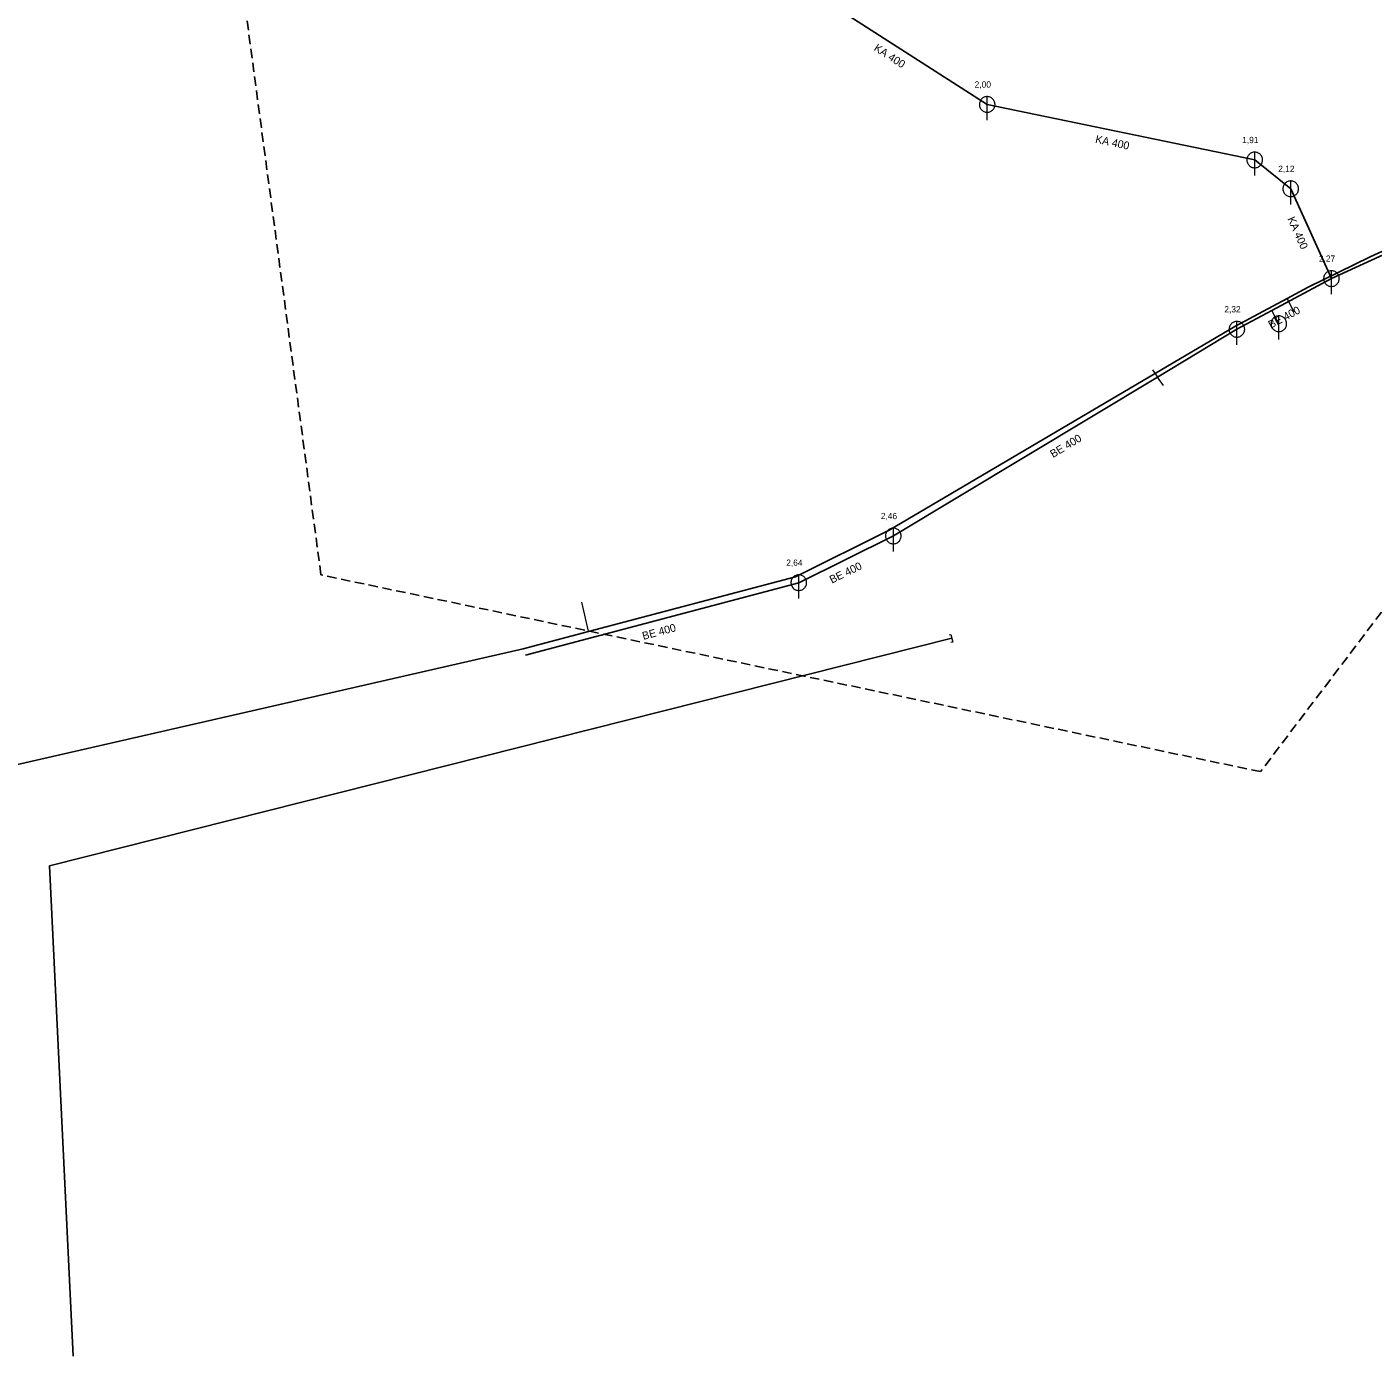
# Model space of a CAD drawing. Extents: x -682839 to -682312, y -994645 to -993949.
# Drawn here: x -682722 to -682550, y -994644.7 to -994475 of the extents above; entities that cross this region are included whole.
import ezdxf

# ---------------------------------------------------------------- set-up
doc = ezdxf.new("R2010")
doc.units = 0
doc.header["$LTSCALE"] = 0.4
doc.linetypes.add('MEDIUM_DASHED', pattern=[4.5, 3, -1.5])
doc.layers.add('1', color=7, linetype='Continuous')
for name, color, linetype, lineweight in [('11', 7, 'Continuous', 13), ('13', 7, 'Continuous', 13), ('14', 7, 'Continuous', 25), ('17', 7, 'Continuous', 25), ('22', 7, 'Continuous', 13), ('34', 7, 'Continuous', 13), ('47', 7, 'Continuous', 13), ('63', 7, 'MEDIUM_DASHED', 25)]:
    doc.layers.add(name, color=color, linetype=linetype, lineweight=lineweight)

msp = doc.modelspace()

# ---------------------------------------------------------------- linework, layer by layer
at = {"layer": '11'}
for p, q in [((-682562.07, -994512.859), (-682562.98, -994511.19)), ((-682578.192, -994518.761), (-682577.559, -994519.67)), ((-682576.8, -994520.77), (-682577.559, -994519.67))]:
    msp.add_line(p, q, dxfattribs=at)
at = {"layer": '13'}
for p, q in [((-682560.989, -994509.68), (-682560.16, -994511.35)), ((-682650.241, -994552.121), (-682651.109, -994548.41))]:
    msp.add_line(p, q, dxfattribs=at)
at = {"layer": '14'}
for p, q in [((-682621.25, -994470.809), (-682599.32, -994484.859)), ((-682599.32, -994484.859), (-682565.149, -994491.949)), ((-682523.789, -994492.6), (-682555.35, -994507.1)), ((-682611.309, -994539.969), (-682623.39, -994545.93)), ((-682623.39, -994545.93), (-682658.3, -994555.18))]:
    msp.add_line(p, q, dxfattribs=at)
at = {"layer": '14', "lineweight": 13}
msp.add_line((-682561.019, -994509.629), (-682560.989, -994509.68), dxfattribs=at)
at = {"layer": '14'}
for points in [[(-682565.149, -994491.949), (-682560.55, -994495.629), (-682555.35, -994507.1)], [(-682555.35, -994507.1), (-682562.98, -994511.19), (-682567.43, -994513.57)], [(-682567.43, -994513.57), (-682577.559, -994519.67), (-682611.309, -994539.969)]]:
    msp.add_lwpolyline(points, dxfattribs=at)
at = {"layer": '17'}
for points in [[(-682545.21, -994501.938), (-682550.42, -994504.32), (-682558.315, -994508.18), (-682561.019, -994509.629), (-682567.699, -994513.21), (-682611.829, -994539.23), (-682623.82, -994545.199), (-682650.23, -994552.17), (-682658.579, -994554.37), (-682723.739, -994569.28), (-682738.277, -994572.726), (-682751.844, -994575.85), (-682782.859, -994582.98), (-682788.5, -994584.28), (-682800.07, -994586.93), (-682812.989, -994588.3), (-682831.809, -994590.289), (-682831.911, -994590.301), (-682838.501, -994590.936)], [(-682716.092, -994644.697), (-682719.099, -994582.077), (-682603.831, -994553.031)]]:
    msp.add_lwpolyline(points, dxfattribs=at)
at = {"layer": '22'}
for p, q in [((-682599.32, -994486.859), (-682599.319, -994483.859)), ((-682565.149, -994493.949), (-682565.148, -994490.949)), ((-682560.55, -994497.629), (-682560.549, -994494.629)), ((-682555.35, -994509.1), (-682555.349, -994506.1)), ((-682567.43, -994515.57), (-682567.429, -994512.57)), ((-682562.07, -994514.859), (-682562.069, -994511.859)), ((-682611.309, -994541.969), (-682611.308, -994538.969)), ((-682623.39, -994547.93), (-682623.389, -994544.93))]:
    msp.add_line(p, q, dxfattribs=at)
for points in [[(-682598.32, -994484.859), (-682598.325, -994484.75), (-682598.343, -994484.642), (-682598.373, -994484.536), (-682598.413, -994484.435), (-682598.465, -994484.338), (-682598.527, -994484.248), (-682598.599, -994484.165), (-682598.679, -994484.091), (-682598.767, -994484.025), (-682598.861, -994483.97), (-682598.961, -994483.925), (-682599.066, -994483.892), (-682599.173, -994483.87), (-682599.282, -994483.86), (-682599.392, -994483.862), (-682599.5, -994483.876), (-682599.607, -994483.901), (-682599.71, -994483.938), (-682599.808, -994483.987), (-682599.9, -994484.045), (-682599.986, -994484.114), (-682600.063, -994484.191), (-682600.132, -994484.277), (-682600.191, -994484.369), (-682600.239, -994484.467), (-682600.276, -994484.57), (-682600.302, -994484.677), (-682600.316, -994484.785), (-682600.319, -994484.895), (-682600.309, -994485.004), (-682600.288, -994485.111), (-682600.254, -994485.215), (-682600.21, -994485.315), (-682600.155, -994485.41), (-682600.089, -994485.498), (-682600.015, -994485.578), (-682599.932, -994485.65), (-682599.842, -994485.712), (-682599.746, -994485.764), (-682599.644, -994485.805), (-682599.539, -994485.835), (-682599.431, -994485.853), (-682599.321, -994485.859), (-682599.212, -994485.853), (-682599.104, -994485.835), (-682598.999, -994485.806), (-682598.897, -994485.765), (-682598.8, -994485.713), (-682598.71, -994485.651), (-682598.627, -994485.58), (-682598.552, -994485.5), (-682598.487, -994485.412), (-682598.431, -994485.318), (-682598.387, -994485.218), (-682598.353, -994485.114), (-682598.331, -994485.006), (-682598.321, -994484.897)], [(-682564.149, -994491.949), (-682564.154, -994491.84), (-682564.172, -994491.732), (-682564.202, -994491.626), (-682564.242, -994491.525), (-682564.294, -994491.428), (-682564.356, -994491.338), (-682564.428, -994491.255), (-682564.508, -994491.181), (-682564.596, -994491.115), (-682564.69, -994491.06), (-682564.79, -994491.015), (-682564.895, -994490.982), (-682565.002, -994490.96), (-682565.111, -994490.95), (-682565.221, -994490.952), (-682565.329, -994490.966), (-682565.436, -994490.991), (-682565.539, -994491.028), (-682565.637, -994491.077), (-682565.729, -994491.135), (-682565.815, -994491.204), (-682565.892, -994491.281), (-682565.961, -994491.367), (-682566.02, -994491.459), (-682566.068, -994491.557), (-682566.105, -994491.66), (-682566.131, -994491.767), (-682566.145, -994491.875), (-682566.148, -994491.985), (-682566.138, -994492.094), (-682566.117, -994492.201), (-682566.083, -994492.305), (-682566.039, -994492.405), (-682565.984, -994492.5), (-682565.918, -994492.588), (-682565.844, -994492.668), (-682565.761, -994492.74), (-682565.671, -994492.802), (-682565.575, -994492.854), (-682565.473, -994492.895), (-682565.368, -994492.925), (-682565.26, -994492.943), (-682565.15, -994492.949), (-682565.041, -994492.943), (-682564.933, -994492.925), (-682564.828, -994492.896), (-682564.726, -994492.855), (-682564.629, -994492.803), (-682564.539, -994492.741), (-682564.456, -994492.67), (-682564.381, -994492.59), (-682564.316, -994492.502), (-682564.26, -994492.408), (-682564.216, -994492.308), (-682564.182, -994492.204), (-682564.16, -994492.096), (-682564.15, -994491.987)], [(-682559.55, -994495.629), (-682559.555, -994495.52), (-682559.573, -994495.412), (-682559.603, -994495.306), (-682559.643, -994495.205), (-682559.695, -994495.108), (-682559.757, -994495.018), (-682559.829, -994494.935), (-682559.909, -994494.861), (-682559.997, -994494.795), (-682560.091, -994494.74), (-682560.191, -994494.695), (-682560.296, -994494.662), (-682560.403, -994494.64), (-682560.512, -994494.63), (-682560.622, -994494.632), (-682560.73, -994494.646), (-682560.837, -994494.671), (-682560.94, -994494.708), (-682561.038, -994494.757), (-682561.13, -994494.815), (-682561.216, -994494.884), (-682561.293, -994494.961), (-682561.362, -994495.047), (-682561.421, -994495.139), (-682561.469, -994495.237), (-682561.506, -994495.34), (-682561.532, -994495.447), (-682561.546, -994495.555), (-682561.549, -994495.665), (-682561.539, -994495.774), (-682561.518, -994495.881), (-682561.484, -994495.985), (-682561.44, -994496.085), (-682561.385, -994496.18), (-682561.319, -994496.268), (-682561.245, -994496.348), (-682561.162, -994496.42), (-682561.072, -994496.482), (-682560.976, -994496.534), (-682560.874, -994496.575), (-682560.769, -994496.605), (-682560.661, -994496.623), (-682560.551, -994496.629), (-682560.442, -994496.623), (-682560.334, -994496.605), (-682560.229, -994496.576), (-682560.127, -994496.535), (-682560.03, -994496.483), (-682559.94, -994496.421), (-682559.857, -994496.35), (-682559.782, -994496.27), (-682559.717, -994496.182), (-682559.661, -994496.088), (-682559.617, -994495.988), (-682559.583, -994495.884), (-682559.561, -994495.776), (-682559.551, -994495.667)], [(-682554.35, -994507.1), (-682554.355, -994506.991), (-682554.373, -994506.883), (-682554.403, -994506.777), (-682554.443, -994506.676), (-682554.495, -994506.579), (-682554.557, -994506.489), (-682554.629, -994506.406), (-682554.709, -994506.332), (-682554.797, -994506.266), (-682554.891, -994506.211), (-682554.991, -994506.166), (-682555.096, -994506.133), (-682555.203, -994506.111), (-682555.312, -994506.101), (-682555.422, -994506.103), (-682555.53, -994506.117), (-682555.637, -994506.142), (-682555.74, -994506.179), (-682555.838, -994506.228), (-682555.93, -994506.286), (-682556.016, -994506.355), (-682556.093, -994506.432), (-682556.162, -994506.518), (-682556.221, -994506.61), (-682556.269, -994506.708), (-682556.306, -994506.811), (-682556.332, -994506.918), (-682556.346, -994507.026), (-682556.349, -994507.136), (-682556.339, -994507.245), (-682556.318, -994507.352), (-682556.284, -994507.456), (-682556.24, -994507.556), (-682556.185, -994507.651), (-682556.119, -994507.739), (-682556.045, -994507.819), (-682555.962, -994507.891), (-682555.872, -994507.953), (-682555.776, -994508.005), (-682555.674, -994508.046), (-682555.569, -994508.076), (-682555.461, -994508.094), (-682555.351, -994508.1), (-682555.242, -994508.094), (-682555.134, -994508.076), (-682555.029, -994508.047), (-682554.927, -994508.006), (-682554.83, -994507.954), (-682554.74, -994507.892), (-682554.657, -994507.821), (-682554.582, -994507.741), (-682554.517, -994507.653), (-682554.461, -994507.559), (-682554.417, -994507.459), (-682554.383, -994507.355), (-682554.361, -994507.247), (-682554.351, -994507.138)], [(-682566.43, -994513.57), (-682566.435, -994513.461), (-682566.453, -994513.353), (-682566.483, -994513.247), (-682566.523, -994513.146), (-682566.575, -994513.049), (-682566.637, -994512.959), (-682566.709, -994512.876), (-682566.789, -994512.802), (-682566.877, -994512.736), (-682566.971, -994512.681), (-682567.071, -994512.636), (-682567.176, -994512.603), (-682567.283, -994512.581), (-682567.392, -994512.571), (-682567.502, -994512.573), (-682567.61, -994512.587), (-682567.717, -994512.612), (-682567.82, -994512.649), (-682567.918, -994512.698), (-682568.01, -994512.756), (-682568.096, -994512.825), (-682568.173, -994512.902), (-682568.242, -994512.988), (-682568.301, -994513.08), (-682568.349, -994513.178), (-682568.386, -994513.281), (-682568.412, -994513.388), (-682568.426, -994513.496), (-682568.429, -994513.606), (-682568.419, -994513.715), (-682568.398, -994513.822), (-682568.364, -994513.926), (-682568.32, -994514.026), (-682568.265, -994514.121), (-682568.199, -994514.209), (-682568.125, -994514.289), (-682568.042, -994514.361), (-682567.952, -994514.423), (-682567.856, -994514.475), (-682567.754, -994514.516), (-682567.649, -994514.546), (-682567.541, -994514.564), (-682567.431, -994514.57), (-682567.322, -994514.564), (-682567.214, -994514.546), (-682567.109, -994514.517), (-682567.007, -994514.476), (-682566.91, -994514.424), (-682566.82, -994514.362), (-682566.737, -994514.291), (-682566.662, -994514.211), (-682566.597, -994514.123), (-682566.541, -994514.029), (-682566.497, -994513.929), (-682566.463, -994513.825), (-682566.441, -994513.717), (-682566.431, -994513.608)], [(-682561.07, -994512.859), (-682561.075, -994512.75), (-682561.093, -994512.642), (-682561.123, -994512.536), (-682561.163, -994512.435), (-682561.215, -994512.338), (-682561.277, -994512.248), (-682561.349, -994512.165), (-682561.429, -994512.091), (-682561.517, -994512.025), (-682561.611, -994511.97), (-682561.711, -994511.925), (-682561.816, -994511.892), (-682561.923, -994511.87), (-682562.032, -994511.86), (-682562.142, -994511.862), (-682562.25, -994511.876), (-682562.357, -994511.901), (-682562.46, -994511.938), (-682562.558, -994511.987), (-682562.65, -994512.045), (-682562.736, -994512.114), (-682562.813, -994512.191), (-682562.882, -994512.277), (-682562.941, -994512.369), (-682562.989, -994512.467), (-682563.026, -994512.57), (-682563.052, -994512.677), (-682563.066, -994512.785), (-682563.069, -994512.895), (-682563.059, -994513.004), (-682563.038, -994513.111), (-682563.004, -994513.215), (-682562.96, -994513.315), (-682562.905, -994513.41), (-682562.839, -994513.498), (-682562.765, -994513.578), (-682562.682, -994513.65), (-682562.592, -994513.712), (-682562.496, -994513.764), (-682562.394, -994513.805), (-682562.289, -994513.835), (-682562.181, -994513.853), (-682562.071, -994513.859), (-682561.962, -994513.853), (-682561.854, -994513.835), (-682561.749, -994513.806), (-682561.647, -994513.765), (-682561.55, -994513.713), (-682561.46, -994513.651), (-682561.377, -994513.58), (-682561.302, -994513.5), (-682561.237, -994513.412), (-682561.181, -994513.318), (-682561.137, -994513.218), (-682561.103, -994513.114), (-682561.081, -994513.006), (-682561.071, -994512.897)], [(-682610.309, -994539.969), (-682610.314, -994539.86), (-682610.332, -994539.752), (-682610.362, -994539.646), (-682610.402, -994539.545), (-682610.454, -994539.448), (-682610.516, -994539.358), (-682610.588, -994539.275), (-682610.668, -994539.201), (-682610.756, -994539.135), (-682610.85, -994539.08), (-682610.95, -994539.035), (-682611.055, -994539.002), (-682611.162, -994538.98), (-682611.271, -994538.97), (-682611.381, -994538.972), (-682611.489, -994538.986), (-682611.596, -994539.011), (-682611.699, -994539.048), (-682611.797, -994539.097), (-682611.889, -994539.155), (-682611.975, -994539.224), (-682612.052, -994539.301), (-682612.121, -994539.387), (-682612.18, -994539.479), (-682612.228, -994539.577), (-682612.265, -994539.68), (-682612.291, -994539.787), (-682612.305, -994539.895), (-682612.308, -994540.005), (-682612.298, -994540.114), (-682612.277, -994540.221), (-682612.243, -994540.325), (-682612.199, -994540.425), (-682612.144, -994540.52), (-682612.078, -994540.608), (-682612.004, -994540.688), (-682611.921, -994540.76), (-682611.831, -994540.822), (-682611.735, -994540.874), (-682611.633, -994540.915), (-682611.528, -994540.945), (-682611.42, -994540.963), (-682611.31, -994540.969), (-682611.201, -994540.963), (-682611.093, -994540.945), (-682610.988, -994540.916), (-682610.886, -994540.875), (-682610.789, -994540.823), (-682610.699, -994540.761), (-682610.616, -994540.69), (-682610.541, -994540.61), (-682610.476, -994540.522), (-682610.42, -994540.428), (-682610.376, -994540.328), (-682610.342, -994540.224), (-682610.32, -994540.116), (-682610.31, -994540.007)], [(-682622.39, -994545.93), (-682622.395, -994545.821), (-682622.413, -994545.713), (-682622.443, -994545.607), (-682622.483, -994545.506), (-682622.535, -994545.409), (-682622.597, -994545.319), (-682622.669, -994545.236), (-682622.749, -994545.162), (-682622.837, -994545.096), (-682622.931, -994545.041), (-682623.031, -994544.996), (-682623.136, -994544.963), (-682623.243, -994544.941), (-682623.352, -994544.931), (-682623.462, -994544.933), (-682623.57, -994544.947), (-682623.677, -994544.972), (-682623.78, -994545.009), (-682623.878, -994545.058), (-682623.97, -994545.116), (-682624.056, -994545.185), (-682624.133, -994545.262), (-682624.202, -994545.348), (-682624.261, -994545.44), (-682624.309, -994545.538), (-682624.346, -994545.641), (-682624.372, -994545.748), (-682624.386, -994545.856), (-682624.389, -994545.966), (-682624.379, -994546.075), (-682624.358, -994546.182), (-682624.324, -994546.286), (-682624.28, -994546.386), (-682624.225, -994546.481), (-682624.159, -994546.569), (-682624.085, -994546.649), (-682624.002, -994546.721), (-682623.912, -994546.783), (-682623.816, -994546.835), (-682623.714, -994546.876), (-682623.609, -994546.906), (-682623.501, -994546.924), (-682623.391, -994546.93), (-682623.282, -994546.924), (-682623.174, -994546.906), (-682623.069, -994546.877), (-682622.967, -994546.836), (-682622.87, -994546.784), (-682622.78, -994546.722), (-682622.697, -994546.651), (-682622.622, -994546.571), (-682622.557, -994546.483), (-682622.501, -994546.389), (-682622.457, -994546.289), (-682622.423, -994546.185), (-682622.401, -994546.077), (-682622.391, -994545.968)]]:
    msp.add_lwpolyline(points, close=True, dxfattribs=at)
at = {"layer": '34'}
msp.add_line((-682560.556, -994509.429), (-682561.421, -994509.93), dxfattribs=at)
at = {"layer": '47'}
msp.add_lwpolyline([(-682604.197, -994552.611), (-682603.953, -994552.55), (-682603.71, -994553.511), (-682603.955, -994553.573)], dxfattribs=at)
at = {"layer": '63'}
msp.add_lwpolyline([(-682494.62, -994477.955), (-682564.4, -994570.065), (-682564.4, -994570.065), (-682684.423, -994544.944), (-682684.423, -994544.944), (-682751.412, -994042.525), (-682751.412, -994042.525), (-682670.466, -994042.525), (-682670.466, -994042.525)], close=True, dxfattribs=at)

# ---------------------------------------------------------------- texts
at = {"layer": '1'}
for s, rotation, p in [('KA 400', 327, (-682613.881, -994477.887)), ('KA 400', 348, (-682585.575, -994489.739)), ('KA 400', 294, (-682560.996, -994499.452)), ('BE 400', 28, (-682563.095, -994513.503)), ('BE 400', 31, (-682590.913, -994530.021)), ('BE 400', 26, (-682619.161, -994546.056)), ('BE 400', 15, (-682643.235, -994553.241))]:
    msp.add_text(s, height=1, rotation=rotation, dxfattribs=at).set_placement(p)
for s, p in [('2,00', (-682600.92, -994482.707)), ('1,91', (-682566.75, -994489.797)), ('2,12', (-682562.15, -994493.477)), ('2,27', (-682556.949, -994504.947)), ('2,32', (-682569.029, -994511.417)), ('2,46', (-682612.91, -994537.817)), ('2,64', (-682624.99, -994543.777))]:
    msp.add_text(s, height=0.8, dxfattribs=at).set_placement(p)

doc.saveas('drawing.dxf')
